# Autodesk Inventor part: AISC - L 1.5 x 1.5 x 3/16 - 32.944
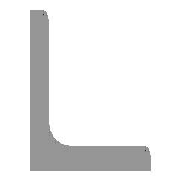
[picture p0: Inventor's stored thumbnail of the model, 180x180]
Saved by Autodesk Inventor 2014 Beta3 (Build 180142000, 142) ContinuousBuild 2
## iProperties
Created: 2010-11
Part Number: AISC - L 1.5 x 1.5 x 3/16 - 32.944
Material: Steel, Mild
Description: Angle Steel
Document SubType Name: Modeling
Standard: ANSI
Designer: Beta-8540w
Standards Organization: ANSI
Language: en-US
Size Designation: L 1.5 x 1.5 x 3/16
Categories: <MemberInstance><Categories><Category DisplayName="Structural Shapes" InternalName="089c4875-fa83-4c05-b084-43b9cc11f5ed" Mnemonic="GRDR"><CategoryParameter Dis
Stock Number: L 1.5 x 1.5 x 3/16
Density: 7.86 g/cm^3
Appearance: Steel
_CCFamilyMember: 5
_CCFamilyDisplayName: ANSI L (Equal angles) - Angle Steel
_FrameMemberDoc: Frame Member File
_Version: 15.0.0
_GetPNFromCC: 1
IsCustomPart: 1
G_L: 32.944 in
G_W: 1.500 in
G_H: 1.500 in
Author: Beta-8540w
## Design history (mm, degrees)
node "Start plane"
node "End plane"
sketch "Sketch"
  geometry: L1 (38.1, 0)-(0, 0); L2 (0, 0)-(0, 38.1); L3 (0, 38.1)-(2.476, 38.1); L4 (4.762, 35.814)-(4.762, 9.589); L5 (9.588, 4.763)-(35.814, 4.763); L6 (38.1, 2.477)-(38.1, 0); L7 (0, -11.041)-(0, 31.538); L8 (-11.041, 0)-(31.538, 0); L9 (0, 48.496)-(0, -20.964) reference; L10 (-20.964, 0)-(48.496, 0) reference; A1 r 4.826 centre (9.588, 9.589) between (4.762, 9.589) and (9.588, 4.763); A2 r 2.286 centre (2.476, 35.814) between (4.762, 35.814) and (2.476, 38.1); A3 r 2.286 centre (35.814, 2.477) between (38.1, 2.477) and (35.814, 4.763); 3 further points
  constraints: 16 end point, 6 point on circle, 6 point on line, 6 tangent, 4 parallel, 3 centre point, 2 collinear, 1 equal radius, 1 horizontal, 1 perpendicular
  dimensions: "d0" = 38.1 distance between parallel lines of L6 L2 (= G_H); "d1" = 38.1 distance between parallel lines of L3 L1 (= G_H); "d2" = 4.7625 distance between parallel lines of L2 L4 (= G_T); "d3" = 4.7625 distance between parallel lines of L1 L5 (= G_T); "d10" = 0 distance between parallel lines of L7 L2 (computed from ex); "d11" = 0 distance between parallel lines of L8 L1 (computed from d10); "d14" = 4.826 radius of A1 (= G_IR); "d15" = 2.286 radius of A2 (= G_ER)
extrude "Body" new body sketch "Sketch" stored distance "d4" = 836.76542 (= G_L); taper "d5" = 0 deg
node "Driven Length"
  sketch "Sketch3"
    geometry: L1 (0, 0)-(10, 0) reference
    constraints: 2 end point, 1 horizontal
  workplane "Work Plane3"
  sketch "Sketch4"
    geometry: L1 (-2, 0)-(12, 0) reference; L2 (-2, 836.765)-(12, 836.765) reference
    dimensions: "d17" = 836.76542 distance between parallel lines of L1 L2 (derived)
body "Solid1"
other parameters: "G_H" = 38.1 [user parameter; used in 2 equation terms], "G_T" = 4.7625 [user parameter; used in 2 equation terms], "G_ER" = 2.286 [user parameter; used in 1 equation term], "G_IR" = 4.826 [user parameter; used in 1 equation term], "G_L" = 836.76542 (= d17) [user parameter; used in 1 equation term], "ex" = 0 [user parameter; used in 1 equation term], "G_OFFSET_START" = 0 [user parameter; used in 1 equation term], "G_OFFSET_END" = 0 [user parameter; used in 1 equation term], "d12" = 0 (computed from G_OFFSET_START), "d13" = 836.76542 (= G_OFFSET_END + B_L), "B_L" = 836.76542 [user parameter; used in 1 equation term], "d16" = 90 deg, "MAS" = 0.26787 [user parameter]
